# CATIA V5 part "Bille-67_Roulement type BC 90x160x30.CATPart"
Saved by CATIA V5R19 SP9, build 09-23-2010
Part number: Bille-67_Roulement type BC 90x160x30
Revision: ANY
Definition: UNKNOWN
Nomenclature: Bille-67_Roulement type BC 90x160x30
Source: Unknown
Bounding box of the stored display mesh (mm): x -8.876 to 8.876, y -8.876 to 8.876, z -8.876 to 8.876
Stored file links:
  Y:\fin de projet cabestan poupee\Bille-67_Roulement type BC 90x160x30.CATPart
  Ass_arbre poupee_1.CATProduct
  Y:\bricolage cabestan\6_axe.CATPart
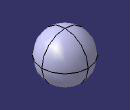
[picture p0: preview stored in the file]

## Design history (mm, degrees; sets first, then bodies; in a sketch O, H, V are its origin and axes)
Body1 "NONE" (main body)
  Solid1: solid without history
